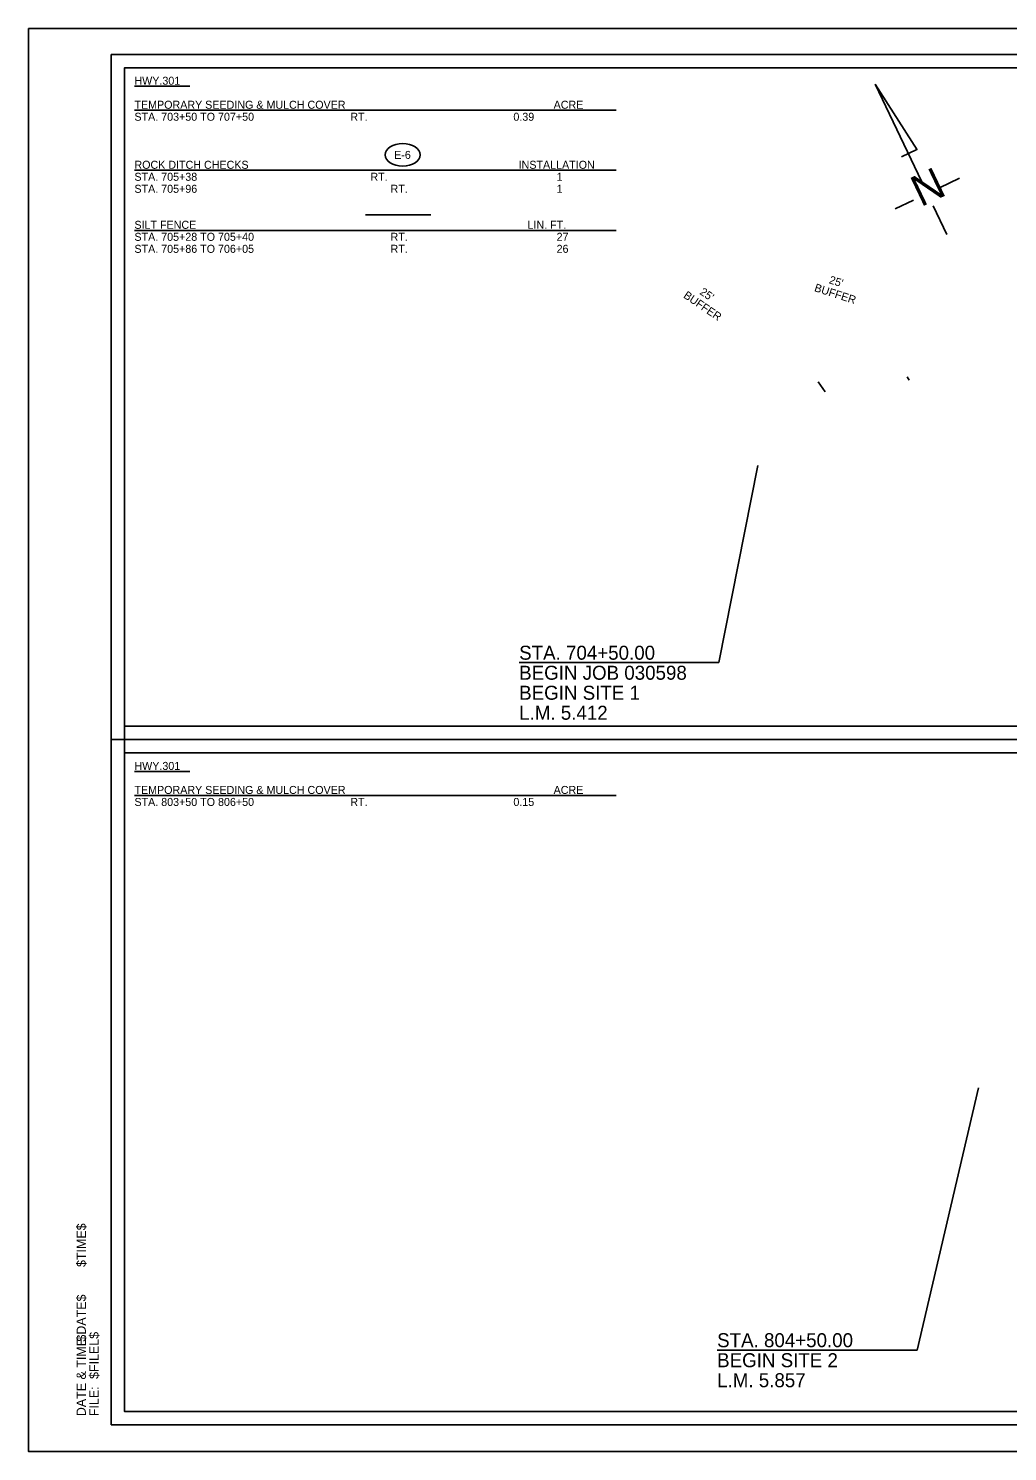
# Model space of a CAD drawing. Extents: x 814841 to 962585, y -174183 to 1802800.
# Drawn here: x 816971 to 817705, y 1801733 to 1802800 of the extents above; entities that cross this region are included whole.
import ezdxf

# ---------------------------------------------------------------- set-up
doc = ezdxf.new("R2010")
doc.units = 0
for name, color, linetype in [('Default', 7, 'Continuous'), ('Erosion Legend', 7, 'Continuous'), ('R_Border', 7, 'Continuous'), ('R_Border Notes', 7, 'Continuous'), ('R_Border Plan-Plan', 7, 'Continuous'), ('R_Detour Annot', 7, 'Continuous'), ('R_Draft', 7, 'Continuous'), ('R_No Plot', 7, 'Continuous'), ('Veg Buffer', 7, 'Continuous'), ('Veg Buffer_Annot', 7, 'Continuous')]:
    doc.layers.add(name, color=color, linetype=linetype)

# ---------------------------------------------------------------- blocks, each defined once
blk = doc.blocks.new('E-6')
at = {"layer": 'Default'}
blk.add_ellipse((0, 0), major_axis=(13.2, 0), ratio=0.638788, dxfattribs=at)
blk.add_text('E-6', height=6, dxfattribs=at).set_placement((-6.4, -3))

msp = doc.modelspace()

# ---------------------------------------------------------------- linework, layer by layer
at = {"layer": 'Erosion Legend'}
for p, q in [((817050.5, 1802756.8), (817092.1, 1802756.8)), ((817050.5, 1802738.8), (817411.5, 1802738.8)), ((817050.5, 1802693.8), (817411.5, 1802693.8)), ((817223.6, 1802660.4), (817272.6, 1802660.4)), ((817050.5, 1802648.6), (817411.5, 1802648.6)), ((817050.5, 1802243.2), (817092.1, 1802243.2)), ((817050.5, 1802225.2), (817411.5, 1802225.2))]:
    msp.add_line(p, q, dxfattribs=at)
at = {"layer": 'R_Border'}
for p, q in [((817033.1, 1802780.6), (818614, 1802780.6)), ((817033.1, 1801753.3), (817033.1, 1802780.6)), ((817033.1, 1801753.3), (817033.1, 1801753.3)), ((818614, 1801753.3), (817033.1, 1801753.3))]:
    msp.add_line(p, q, dxfattribs=at)
at = {"layer": 'R_Border Plan-Plan'}
msp.add_line((817033.1, 1802267), (818614, 1802267), dxfattribs=at)
at = {"layer": 'R_Draft'}
for p, q in [((817605.7, 1802758.4), (817637.3, 1802709)), ((817640.7, 1802685), (817605.7, 1802758.4)), ((817625.5, 1802703.8), (817637.1, 1802709.4)), ((817654.1, 1802680.7), (817669, 1802687.8)), ((817620.7, 1802664.8), (817634.6, 1802671.4)), ((817659.5, 1802645.6), (817649.2, 1802667.2)), ((817488.6, 1802324.7), (817517.7, 1802472.5)), ((817488.6, 1802324.7), (817338.9, 1802324.7)), ((817637.3, 1801809.3), (817683.2, 1802006.1)), ((817637.3, 1801809.3), (817487.3, 1801809.3))]:
    msp.add_line(p, q, dxfattribs=at)
at = {"layer": 'R_No Plot'}
for points in [[(816971.1, 1802800.1), (818637.8, 1802800.1), (818637.8, 1801733.4), (816971.1, 1801733.4)], [(818604, 1802277), (817043.1, 1802277), (817043.1, 1802770.6), (818290.8, 1802770.6), (818290.8, 1802721.2), (818378.5, 1802721.2), (818499, 1802721.2), (818499, 1802609.5), (818604, 1802609.5)], [(818604, 1802277), (817043.1, 1802277), (817043.1, 1802770.6), (818290.8, 1802770.6), (818290.8, 1802721.2), (818378.5, 1802721.2), (818499, 1802721.2), (818499, 1802609.5), (818604, 1802609.5)], [(818604, 1802277), (817043.1, 1802277), (817043.1, 1802770.6), (818290.8, 1802770.6), (818290.8, 1802721.2), (818378.5, 1802721.2), (818499, 1802721.2), (818499, 1802609.5), (818604, 1802609.5)], [(818604, 1802277), (817043.1, 1802277), (817043.1, 1802770.6), (818290.8, 1802770.6), (818290.8, 1802721.2), (818378.5, 1802721.2), (818499, 1802721.2), (818499, 1802609.5), (818604, 1802609.5)], [(818604, 1802277), (817043.1, 1802277), (817043.1, 1802770.6), (818290.8, 1802770.6), (818290.8, 1802721.2), (818378.5, 1802721.2), (818499, 1802721.2), (818499, 1802609.5), (818604, 1802609.5)], [(818604, 1802277), (817043.1, 1802277), (817043.1, 1802770.6), (818290.8, 1802770.6), (818290.8, 1802721.2), (818378.5, 1802721.2), (818499, 1802721.2), (818499, 1802609.5), (818604, 1802609.5)], [(817043.1, 1802770.6), (818290.8, 1802770.6), (818290.8, 1802721.2), (818378.5, 1802721.2), (818499, 1802721.2), (818499, 1802609.5), (818604, 1802609.5), (818604, 1801763.3), (817043.1, 1801763.3)], [(818604, 1802277), (817043.1, 1802277), (817043.1, 1802770.6), (818290.8, 1802770.6), (818290.8, 1802721.2), (818378.5, 1802721.2), (818499, 1802721.2), (818499, 1802609.5), (818604, 1802609.5)], [(817043.1, 1802257), (818604, 1802257), (818604, 1801763.3), (817043.1, 1801763.3)], [(817043.1, 1802257), (818604, 1802257), (818604, 1801763.3), (817043.1, 1801763.3)], [(817043.1, 1802257), (818604, 1802257), (818604, 1801763.3), (817043.1, 1801763.3)], [(817043.1, 1802257), (818604, 1802257), (818604, 1801763.3), (817043.1, 1801763.3)], [(817043.1, 1802257), (818604, 1802257), (818604, 1801763.3), (817043.1, 1801763.3)], [(817043.1, 1802257), (818604, 1802257), (818604, 1801763.3), (817043.1, 1801763.3)], [(817043.1, 1802257), (818604, 1802257), (818604, 1801763.3), (817043.1, 1801763.3)]]:
    msp.add_lwpolyline(points, close=True, dxfattribs=at)
at = {"layer": 'Veg Buffer'}
for p, q in [((817568.3, 1802527.6), (817563, 1802535.1)), ((817631.3, 1802536.4), (817629.8, 1802539))]:
    msp.add_line(p, q, dxfattribs=at)

# ---------------------------------------------------------------- block references
at = {"layer": 'Erosion Legend', "rotation": -1.8065126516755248e-10}
msp.add_blockref('E-6', (817251.6, 1802705.3), dxfattribs=at)

# ---------------------------------------------------------------- texts
at = {"layer": 'Erosion Legend'}
for s, p in [('HWY.301', (817050.5, 1802757.9)), ('TEMPORARY SEEDING & MULCH COVER', (817050.5, 1802739.9)), (' ACRE', (817362.5, 1802739.9)), ('STA. 703+50 TO 707+50', (817050.5, 1802730.9)), ('        RT.    ', (817194.5, 1802730.9)), ('         0.39', (817314.5, 1802730.9)), ('ROCK DITCH CHECKS', (817050.5, 1802694.9)), ('INSTALLATION', (817338.5, 1802694.9)), ('STA. 705+38   ', (817050.5, 1802685.9)), ('STA. 705+96', (817050.5, 1802676.9)), ('    RT.', (817218.5, 1802685.9)), ('RT.', (817242.5, 1802676.9)), ('  1', (817362.5, 1802685.9)), ('  1', (817362.5, 1802676.9)), ('SILT FENCE', (817050.5, 1802649.9)), ('   LIN. FT.', (817338.5, 1802649.9)), ('STA. 705+28 TO 705+40', (817050.5, 1802640.9)), ('RT.', (817242.5, 1802640.9)), ('  27', (817362.5, 1802640.9)), ('STA. 705+86 TO 706+05', (817050.5, 1802631.9)), ('RT.  ', (817242.5, 1802631.9)), ('  26', (817362.5, 1802631.9)), ('HWY.301', (817050.5, 1802244.3)), ('TEMPORARY SEEDING & MULCH COVER', (817050.5, 1802226.3)), ('STA. 803+50 TO 806+50', (817050.5, 1802217.3)), ('        RT.    ', (817194.5, 1802217.3)), ('         0.15', (817314.5, 1802217.3)), (' ACRE', (817362.5, 1802226.3))]:
    msp.add_text(s, height=6, dxfattribs=at).set_placement(p)
at = {"layer": 'R_Border Notes'}
for s, height, p in [('$TIME$', 6.98, (817014.1, 1801871.7)), ('$DATE$', 6.98, (817014.1, 1801815.8)), ('DATE & TIME:', 6.984, (817014.1, 1801759.9)), ('$FILEL$', 6.98, (817023.7, 1801787.8)), ('FILE: ', 6.98, (817023.7, 1801759.9))]:
    msp.add_text(s, height=height, rotation=90, dxfattribs=at).set_placement(p)
at = {"layer": 'R_Detour Annot'}
for s, p in [('STA. 704+50.00', (817338.9, 1802326.9)), ('BEGIN JOB 030598 ', (817338.9, 1802311.9)), ('BEGIN SITE 1', (817338.9, 1802296.9)), ('L.M. 5.412', (817338.9, 1802281.9)), ('STA. 804+50.00 ', (817487.3, 1801811.6)), ('BEGIN SITE 2', (817487.3, 1801796.6)), ('L.M. 5.857', (817487.3, 1801781.6))]:
    msp.add_text(s, height=10.5, dxfattribs=at).set_placement(p)
at = {"layer": 'R_Draft'}
msp.add_text('N', height=23.3, rotation=25.5319, dxfattribs=at).set_placement((817640, 1802666))
at = {"layer": 'Veg Buffer_Annot'}
for s, rotation, p in [('BUFFER', 342.1183, (817559.7, 1802603.3)), ("25'", 342.1183, (817570.7, 1802609.2)), ('BUFFER', 325.6564, (817461.5, 1802598.7)), ("25'", 325.6564, (817473.7, 1802601.3))]:
    msp.add_text(s, height=6, rotation=rotation, dxfattribs=at).set_placement(p)

doc.saveas('drawing.dxf')
